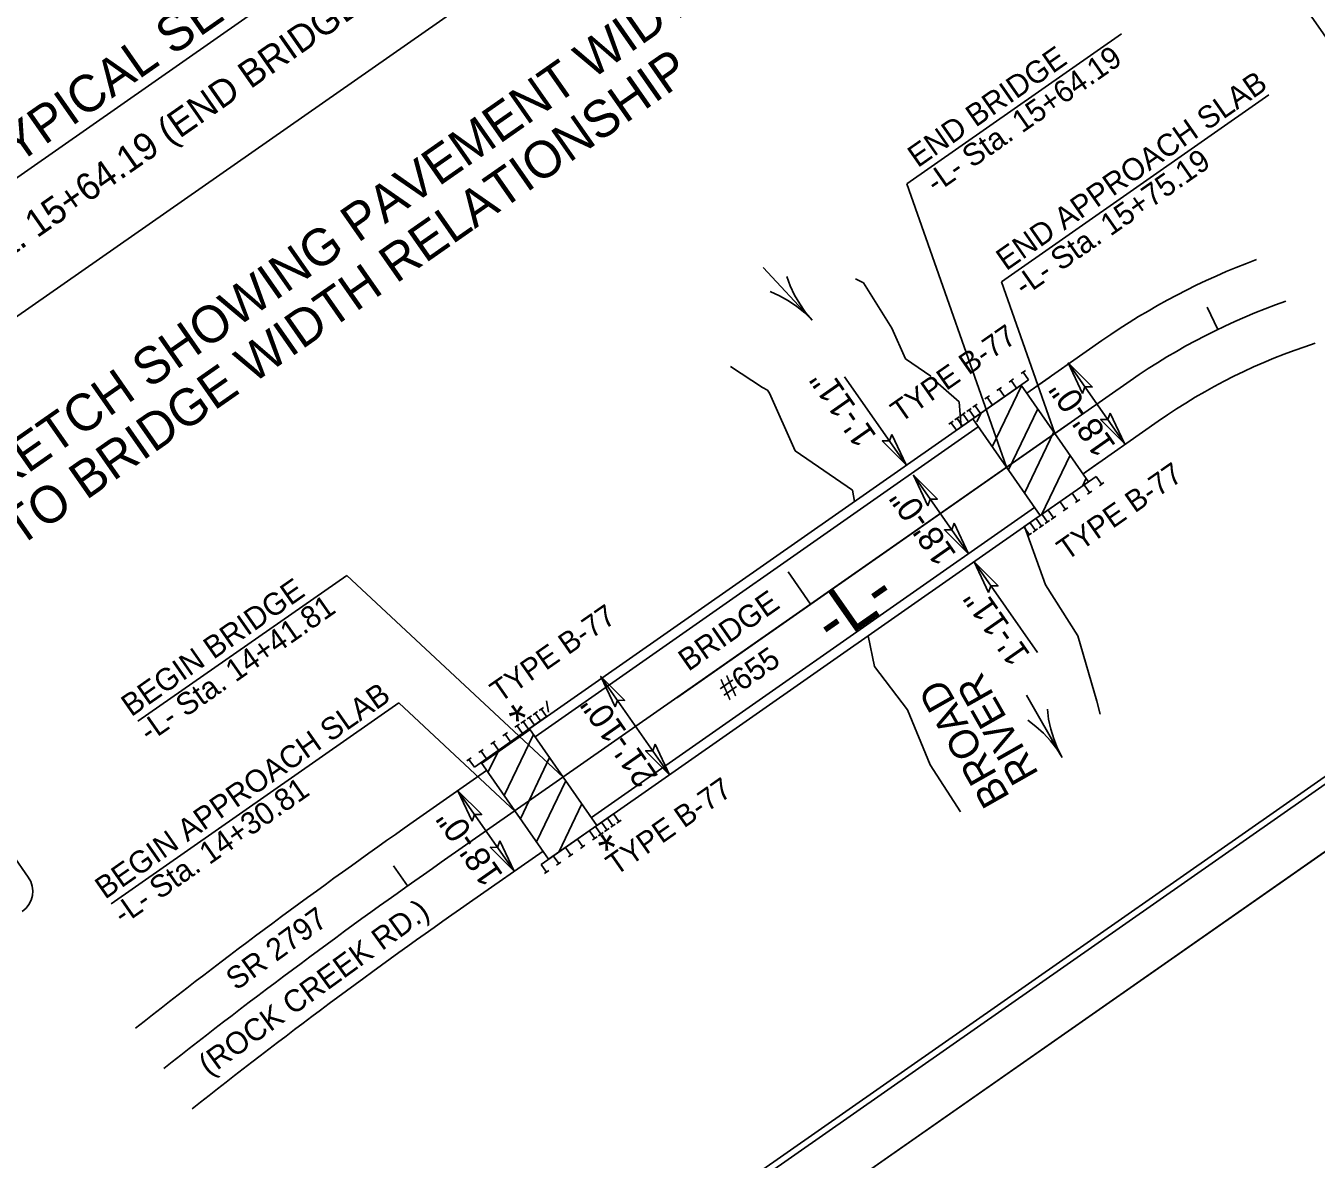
# Model space of a CAD drawing. Extents: x 1033697 to 1037131, y 657437 to 660507.
# Drawn here: x 1036343 to 1036868, y 659180 to 659641 of the extents above; entities that cross this region are included whole.
import ezdxf

# ---------------------------------------------------------------- set-up
doc = ezdxf.new("R2010")
doc.units = 0
for name, color, linetype in [('Default', 7, 'Continuous'), ('Exist PHM Water Shape', 7, 'Continuous'), ('Old_Level_23', 7, 'Continuous'), ('Old_Level_25', 7, 'Continuous'), ('Old_Level_30', 7, 'Continuous'), ('Prop Approach Slab', 7, 'Continuous'), ('Prop Approach Slab Hatching', 7, 'Continuous'), ('Prop EOT', 7, 'Continuous'), ('Prop Horizontal Alignment', 7, 'Continuous'), ('Prop Horizontal Alignment Tick Large', 7, 'Continuous'), ('Prop Horizontal Alignment Tick Small', 7, 'Continuous'), ('Prop Pavement Schedule Description CELL', 7, 'Continuous'), ('Prop Roadway Bridge', 7, 'Continuous'), ('Prop Structure Anchor Unit CELL', 7, 'Continuous'), ('Prop Terminator CELL', 7, 'Continuous'), ('Sheet Cutting Line CELL', 7, 'Continuous'), ('Sheet Plot Border Inside CELL', 7, 'Continuous'), ('Sheet Plot Border Outside CELL', 7, 'Continuous'), ('Sheet Title CELL', 7, 'Continuous'), ('Sheet Typical CELL', 7, 'Continuous'), ('Typical Text General CELL', 7, 'Continuous'), ('Typical Text Label CELL', 7, 'Continuous')]:
    doc.layers.add(name, color=color, linetype=linetype)

msp = doc.modelspace()

# ---------------------------------------------------------------- linework, layer by layer
at = {"layer": 'Default'}
for p, q in [((1035521.13, 658950.73), (1036750.78, 659809.79)), ((1036701.64, 659576.5), (1036789.03, 659637.58)), ((1036740.15, 659536.75), (1036848.97, 659612.81)), ((1036742.21, 659461.26), (1036701.64, 659576.5)), ((1036663.12, 659521.15), (1036643.28, 659542.5)), ((1036652.86, 659538.92), (1036654.27, 659535.08)), ((1036649.5, 659535.81), (1036649.5, 659535.81)), ((1036654.27, 659535.08), (1036656.03, 659531.32)), ((1036761.88, 659475.01), (1036740.15, 659536.75)), ((1036646.15, 659532.69), (1036649.88, 659531)), ((1036649.88, 659531), (1036653.5, 659528.97)), ((1036653.5, 659528.97), (1036656.97, 659526.63)), ((1036656.03, 659531.32), (1036658.1, 659527.69)), ((1036656.97, 659526.63), (1036660.22, 659524.05)), ((1036658.1, 659527.69), (1036660.44, 659524.26)), ((1036660.22, 659524.05), (1036663.12, 659521.15)), ((1036660.44, 659524.26), (1036663.12, 659521.15)), ((1036767.34, 659503.69), (1036790.26, 659470.91)), ((1036676.38, 659498.08), (1036701.43, 659462.24)), ((1036676.38, 659498.08), (1036701.43, 659462.24)), ((1036550.43, 659351.62), (1036730.75, 659477.65)), ((1036704.38, 659458.02), (1036726.73, 659426.04)), ((1036573.35, 659318.83), (1036753.67, 659444.87)), ((1036729.02, 659422.76), (1036754.82, 659385.86)), ((1036388.86, 659357.89), (1036473.84, 659417.28)), ((1036561.89, 659335.23), (1036473.84, 659417.28)), ((1036577.64, 659375.51), (1036605.13, 659336.17)), ((1036764.83, 659343.24), (1036750.3, 659368.5)), ((1036377.95, 659283.59), (1036494.97, 659365.38)), ((1036542.47, 659321.11), (1036494.97, 659365.38)), ((1036754.86, 659360.58), (1036754.86, 659360.58)), ((1036758.83, 659362.86), (1036759.34, 659358.8)), ((1036750.89, 659358.3), (1036754.14, 659355.81)), ((1036754.14, 659355.81), (1036757.21, 659353.02)), ((1036759.34, 659358.8), (1036760.2, 659354.74)), ((1036757.21, 659353.02), (1036760.07, 659349.96)), ((1036760.07, 659349.96), (1036762.65, 659346.72)), ((1036760.2, 659354.74), (1036761.41, 659350.73)), ((1036761.41, 659350.73), (1036762.91, 659346.87)), ((1036762.65, 659346.72), (1036764.83, 659343.24)), ((1036762.91, 659346.87), (1036764.83, 659343.24)), ((1036519.03, 659329.67), (1036541.94, 659296.89))]:
    msp.add_line(p, q, dxfattribs=at)
at = {"layer": 'Exist PHM Water Shape'}
for points in [[(1036680.81, 659537.84), (1036684.02, 659536.3), (1036695.53, 659517.89), (1036701.14, 659505.38), (1036711.49, 659498.25)], [(1036629.92, 659502.27), (1036642.9, 659493.64), (1036644.98, 659492.64), (1036645.79, 659491.35), (1036656.27, 659467.98), (1036679.6, 659451.92)], [(1036711.3, 659497.99), (1036722.95, 659487.8), (1036723.73, 659477.62)], [(1036679.6, 659451.92), (1036680.4, 659447.34)], [(1036749.59, 659437.14), (1036758.15, 659413.4), (1036771.26, 659392.62), (1036778.96, 659366.14)], [(1036685.94, 659392.65), (1036688.55, 659380.14), (1036701.97, 659362.57), (1036711.16, 659340.2)], [(1036555.06, 659366.26), (1036555.86, 659361.68)], [(1036778.96, 659366.14), (1036780.32, 659360.74)], [(1036711.16, 659340.2), (1036723.52, 659321.04)]]:
    msp.add_lwpolyline(points, dxfattribs=at)
at = {"layer": 'Prop Approach Slab'}
for p, q in [((1036728.46, 659480.93), (1036748.13, 659494.68)), ((1036728.46, 659480.93), (1036748.13, 659494.68)), ((1036775.63, 659455.34), (1036748.13, 659494.68)), ((1036728.46, 659480.93), (1036755.96, 659441.59)), ((1036755.96, 659441.59), (1036775.63, 659455.34)), ((1036528.47, 659341.15), (1036548.39, 659354.54)), ((1036548.39, 659354.54), (1036528.72, 659340.8)), ((1036548.39, 659354.54), (1036528.72, 659340.8)), ((1036575.64, 659315.56), (1036548.14, 659354.9)), ((1036555.97, 659301.81), (1036528.47, 659341.15)), ((1036575.64, 659315.56), (1036555.97, 659301.81)), ((1036575.64, 659315.56), (1036555.97, 659301.81)), ((1036575.64, 659315.56), (1036555.97, 659301.81))]:
    msp.add_line(p, q, dxfattribs=at)
at = {"layer": 'Prop Approach Slab Hatching'}
for p, q in [((1036736.4, 659469.57), (1036748.32, 659494.41)), ((1036730.18, 659479.72), (1036731.92, 659483.35)), ((1036730.18, 659479.72), (1036731.92, 659483.35)), ((1036742.98, 659460.16), (1036754.9, 659485.01)), ((1036749.55, 659450.75), (1036761.47, 659475.6)), ((1036756.39, 659441.89), (1036768.05, 659466.19)), ((1036773.08, 659453.56), (1036774.63, 659456.78)), ((1036537.88, 659327.69), (1036549.8, 659352.53)), ((1036531.3, 659337.1), (1036535.53, 659345.89)), ((1036544.46, 659318.28), (1036556.38, 659343.12)), ((1036551.03, 659308.87), (1036562.95, 659333.71)), ((1036560.14, 659304.72), (1036569.53, 659324.3))]:
    msp.add_line(p, q, dxfattribs=at)
at = {"layer": 'Prop EOT'}
for p, q in [((1036750.43, 659491.4), (1036781.04, 659512.8)), ((1036750.43, 659491.4), (1036759.81, 659497.96)), ((1036773.34, 659458.62), (1036803.96, 659480.02)), ((1036773.34, 659458.62), (1036779.86, 659463.17)), ((1036500.82, 659316.94), (1036530.76, 659337.87)), ((1036523.73, 659284.16), (1036553.68, 659305.09))]:
    msp.add_line(p, q, dxfattribs=at)
for centre, radius, start, end in [((1036941.45, 659283.3), 280, 110.3777, 124.9511), ((1036941.45, 659283.3), 240, 107.88, 124.9511), ((1037887.18, 657333.41), 2420, 124.95105, 128.28032), ((1037887.18, 657333.41), 2380, 124.95105, 128.33633)]:
    msp.add_arc(centre, radius, start, end, dxfattribs=at)
at = {"layer": 'Prop Horizontal Alignment'}
for p, q in [((1036512.28, 659300.55), (1036792.5, 659496.41)), ((1036608.07, 659367.5), (1036769.83, 659480.57))]:
    msp.add_line(p, q, dxfattribs=at)
for centre, radius, start, end in [((1036941.45, 659283.3), 260, 109.2287, 124.9511), ((1037887.18, 657333.41), 2400, 124.95105, 128.30809)]:
    msp.add_arc(centre, radius, start, end, dxfattribs=at)
at = {"layer": 'Prop Horizontal Alignment Tick Large'}
msp.add_line((1036662.51, 659405.55), (1036653.34, 659418.67), dxfattribs=at)
msp.add_line((1036662.51, 659405.55), (1036653.34, 659418.67), dxfattribs=at)
at = {"layer": 'Prop Horizontal Alignment Tick Small'}
for p, q in [((1036828.18, 659517.33), (1036823.82, 659526.33)), ((1036498.61, 659290.93), (1036492.83, 659299.09))]:
    msp.add_line(p, q, dxfattribs=at)
at = {"layer": 'Prop Roadway Bridge'}
for p, q in [((1036548.3, 659355.01), (1036728.46, 659480.93)), ((1036548.3, 659355.01), (1036728.46, 659480.93)), ((1036548.3, 659355.01), (1036728.46, 659480.93)), ((1036575.8, 659315.67), (1036755.96, 659441.59))]:
    msp.add_line(p, q, dxfattribs=at)
at = {"layer": 'Prop Structure Anchor Unit CELL'}
for p, q in [((1036721.84, 659476.3), (1036751.23, 659496.84)), ((1036743.24, 659495.93), (1036745.04, 659497.18)), ((1036748.14, 659499.35), (1036749.93, 659500.61)), ((1036751.23, 659496.84), (1036749.04, 659499.98)), ((1036738.34, 659492.5), (1036740.14, 659493.76)), ((1036741.43, 659490), (1036739.24, 659493.13)), ((1036746.33, 659493.42), (1036744.14, 659496.56)), ((1036728.54, 659485.66), (1036730.34, 659486.91)), ((1036731.63, 659483.15), (1036729.44, 659486.28)), ((1036733.44, 659489.08), (1036735.24, 659490.33)), ((1036736.53, 659486.57), (1036734.34, 659489.71)), ((1036721.2, 659480.52), (1036722.99, 659481.78)), ((1036724.29, 659478.01), (1036722.09, 659481.15)), ((1036723.65, 659482.23), (1036725.44, 659483.49)), ((1036726.73, 659479.72), (1036724.54, 659482.86)), ((1036726.09, 659483.94), (1036727.89, 659485.2)), ((1036729.18, 659481.44), (1036726.99, 659484.57)), ((1036718.75, 659478.81), (1036720.54, 659480.06)), ((1036721.84, 659476.3), (1036719.64, 659479.44)), ((1036749.33, 659436.96), (1036778.73, 659457.5)), ((1036778.73, 659457.5), (1036780.92, 659454.37)), ((1036780.02, 659453.74), (1036781.82, 659454.99)), ((1036768.93, 659450.65), (1036771.12, 659447.52)), ((1036773.83, 659454.08), (1036776.02, 659450.94)), ((1036775.12, 659450.31), (1036776.92, 659451.57)), ((1036764.03, 659447.23), (1036766.22, 659444.09)), ((1036765.32, 659443.47), (1036767.12, 659444.72)), ((1036770.22, 659446.89), (1036772.02, 659448.15)), ((1036754.23, 659440.38), (1036756.42, 659437.25)), ((1036756.68, 659442.09), (1036758.87, 659438.96)), ((1036757.98, 659438.33), (1036759.77, 659439.59)), ((1036759.13, 659443.81), (1036761.32, 659440.67)), ((1036760.42, 659440.04), (1036762.22, 659441.3)), ((1036749.33, 659436.96), (1036751.53, 659433.82)), ((1036750.63, 659433.2), (1036752.42, 659434.45)), ((1036751.78, 659438.67), (1036753.97, 659435.53)), ((1036753.08, 659434.91), (1036754.87, 659436.16)), ((1036755.53, 659436.62), (1036757.32, 659437.87)), ((1036551.41, 659361.85), (1036549.62, 659360.6)), ((1036552.71, 659358.09), (1036550.51, 659361.22)), ((1036553.86, 659363.56), (1036552.07, 659362.31)), ((1036555.15, 659359.8), (1036552.96, 659362.94)), ((1036555.15, 659359.8), (1036525.76, 659339.26)), ((1036544.06, 659356.72), (1036542.27, 659355.46)), ((1036545.36, 659352.95), (1036543.17, 659356.09)), ((1036546.51, 659358.43), (1036544.72, 659357.17)), ((1036547.81, 659354.67), (1036545.62, 659357.8)), ((1036548.96, 659360.14), (1036547.17, 659358.88)), ((1036550.26, 659356.38), (1036548.06, 659359.51)), ((1036534.27, 659349.87), (1036532.47, 659348.61)), ((1036539.17, 659353.29), (1036537.37, 659352.04)), ((1036540.46, 659349.53), (1036538.27, 659352.66)), ((1036529.37, 659346.44), (1036527.57, 659345.19)), ((1036530.66, 659342.68), (1036528.47, 659345.82)), ((1036535.56, 659346.11), (1036533.37, 659349.24)), ((1036524.47, 659343.02), (1036522.67, 659341.77)), ((1036525.76, 659339.26), (1036523.57, 659342.39)), ((1036582.36, 659320.26), (1036552.97, 659299.71)), ((1036579.91, 659318.54), (1036582.11, 659315.41)), ((1036582.36, 659320.26), (1036584.56, 659317.12)), ((1036572.57, 659313.41), (1036574.76, 659310.27)), ((1036575.02, 659315.12), (1036577.21, 659311.99)), ((1036577.47, 659316.83), (1036579.66, 659313.7)), ((1036580.55, 659314.33), (1036578.76, 659313.07)), ((1036583, 659316.04), (1036581.21, 659314.78)), ((1036585.45, 659317.75), (1036583.66, 659316.49)), ((1036567.67, 659309.99), (1036569.86, 659306.85)), ((1036575.66, 659310.9), (1036573.86, 659309.65)), ((1036578.11, 659312.61), (1036576.31, 659311.36)), ((1036557.87, 659303.14), (1036560.06, 659300)), ((1036562.77, 659306.56), (1036564.96, 659303.43)), ((1036565.86, 659304.05), (1036564.06, 659302.8)), ((1036570.76, 659307.48), (1036568.96, 659306.22)), ((1036552.97, 659299.71), (1036555.16, 659296.58)), ((1036560.96, 659300.63), (1036559.16, 659299.37)), ((1036556.06, 659297.21), (1036554.27, 659295.95))]:
    msp.add_line(p, q, dxfattribs=at)
at = {"layer": 'Prop Terminator CELL'}
for points in [[(1036773.17, 659491.3), (1036767.34, 659503.69), (1036777.09, 659493.94), (1036774.13, 659493.98)], [(1036784.43, 659483.31), (1036790.26, 659470.91), (1036780.51, 659480.66), (1036783.47, 659480.62)], [(1036695.6, 659474.64), (1036701.43, 659462.24), (1036691.69, 659471.99), (1036694.64, 659471.95)], [(1036710.21, 659445.62), (1036704.38, 659458.02), (1036714.12, 659448.27), (1036711.17, 659448.31)], [(1036720.9, 659438.44), (1036726.73, 659426.04), (1036716.99, 659435.79), (1036719.94, 659435.75)], [(1036734.85, 659410.36), (1036729.02, 659422.76), (1036738.77, 659413.01), (1036735.81, 659413.05)], [(1036583.01, 659363.76), (1036577.18, 659376.16), (1036586.93, 659366.41), (1036583.97, 659366.45)], [(1036599.31, 659348.57), (1036605.13, 659336.17), (1036595.39, 659345.92), (1036598.35, 659345.88)], [(1036524.86, 659317.27), (1036519.03, 659329.67), (1036528.77, 659319.92), (1036525.82, 659319.96)], [(1036536.12, 659309.28), (1036541.94, 659296.89), (1036532.2, 659306.64), (1036535.16, 659306.6)]]:
    msp.add_lwpolyline(points, close=True, dxfattribs=at)
at = {"layer": 'Sheet Cutting Line CELL'}
for p, q in [((1035661.22, 658458.77), (1037041.5, 659423.5)), ((1037041.5, 659423.5), (1035661.22, 658458.77))]:
    msp.add_line(p, q, dxfattribs=at)
at = {"layer": 'Sheet Plot Border Inside CELL'}
msp.add_lwpolyline([(1036420.5, 660304.13), (1035054.57, 659349.42), (1035659.01, 658484.62), (1037024.95, 659439.32)], close=True, dxfattribs=at)
at = {"layer": 'Sheet Plot Border Outside CELL'}
msp.add_lwpolyline([(1036411.33, 660325.1), (1035031.05, 659360.38), (1035661.22, 658458.77), (1037041.5, 659423.5)], close=True, dxfattribs=at)
at = {"layer": 'Sheet Title CELL'}
msp.add_line((1036252.65, 659425.63), (1036344.31, 659294.49), dxfattribs=at)
msp.add_arc((1036336.11, 659288.76), 10, 304.9512, 34.9512, dxfattribs=at)
at = {"layer": 'Sheet Typical CELL'}
msp.add_lwpolyline([(1036411.72, 660294.87), (1035182.26, 659435.56), (1035783.78, 658574.94), (1037013.24, 659434.25)], close=True, dxfattribs=at)
at = {"layer": 'Typical Text Label CELL'}
msp.add_line((1036329.35, 659571.88), (1036532.58, 659713.86), dxfattribs=at)

# ---------------------------------------------------------------- texts
at = {"layer": 'Default'}
for s, height, rotation, p in [('END BRIDGE', 9, 34.9389, (1036706.13, 659582.88)), ('-L- Sta. 15+64.19', 9, 34.9389, (1036713.43, 659572.43)), ('END APPROACH SLAB', 9, 34.9389, (1036742.1, 659540.95)), ('-L- Sta. 15+75.19', 9, 34.9389, (1036749.4, 659530.5)), ('1\'-11"', 10.125, 124.9512, (1036689.66, 659474.01)), ('18\'-0"', 10.125, 124.9512, (1036787.02, 659470.05)), ('18\'-0"', 10.125, 124.9512, (1036722.15, 659425.85)), ('BEGIN BRIDGE', 9, 34.9389, (1036386.2, 659359.51)), ('-L- Sta. 14+41.81', 9, 34.9389, (1036393.5, 659349.06)), ('1\'-11"', 10.125, 124.9512, (1036752.2, 659385.05)), ('BEGIN APPROACH SLAB', 9, 34.9389, (1036375.55, 659285.27)), ('21\'-10"', 10.125, 124.9512, (1036600.81, 659335.61)), ('*', 13.5, 34.9389, (1036545.95, 659351.22)), ('-L- Sta. 14+30.81', 9, 34.9389, (1036382.85, 659274.82)), ('18\'-0"', 10.125, 124.9512, (1036537.76, 659295.37)), ('*', 13.5, 34.9389, (1036582.29, 659298.57)), ('(ROCK CREEK RD.)', 9, 35.9389, (1036417.79, 659213.33)), ('SR 2797', 9, 35.9389, (1036428.89, 659248.12))]:
    msp.add_text(s, height=height, rotation=rotation, dxfattribs=at).set_placement(p)
at = {"layer": 'Old_Level_23'}
msp.add_text('-L-', height=20, rotation=34.9512, dxfattribs=at).set_placement((1036671.79, 659388.06))
at = {"layer": 'Old_Level_25'}
for s, p in [('BRIDGE', (1036612.82, 659377.96)), ('#655', (1036628.91, 659366.02))]:
    msp.add_text(s, height=9, rotation=34.9389, dxfattribs=at).set_placement(p)
at = {"layer": 'Old_Level_30'}
for s, p in [('RIVER', (1036755.54, 659336.52)), ('BROAD ', (1036743.83, 659327.15))]:
    msp.add_text(s, height=11.812, rotation=119.5725, dxfattribs=at).set_placement(p)
at = {"layer": 'Prop Pavement Schedule Description CELL'}
for s, p in [('SKETCH SHOWING PAVEMENT WIDTH', (1036322.14, 659443.2)), ('TO BRIDGE WIDTH RELATIONSHIP', (1036340.47, 659428.56))]:
    msp.add_text(s, height=15, rotation=34.9389, dxfattribs=at).set_placement(p)
at = {"layer": 'Prop Roadway Bridge'}
for p in [(1036699.08, 659479.16), (1036766.69, 659423.04), (1036536.16, 659365.29), (1036583.31, 659294.87)]:
    msp.add_text('TYPE B-77', height=8.75, rotation=34.9512, dxfattribs=at).set_placement(p)
at = {"layer": 'Typical Text General CELL'}
msp.add_text('-L- Sta. 15+64.19 (END BRIDGE) to Sta. 16+51.68 ', height=11, rotation=34.9389, dxfattribs=at).set_placement((1036304.97, 659524.34))
at = {"layer": 'Typical Text Label CELL'}
msp.add_text('TYPICAL SECTION NO. 2', height=15, rotation=34.9389, dxfattribs=at).set_placement((1036329.84, 659577.38))

doc.saveas('drawing.dxf')
